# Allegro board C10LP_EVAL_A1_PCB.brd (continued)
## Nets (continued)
C10_M10_IO3: U1.C3(IO, PLL3_CLKOUTN) U3.L5(IO_3_L5/DIFFIO_TX_RX_B1N)
C10_MSEL0: R22.1 R23.1 U1.H13(MSEL0)
C10_MSEL1: R19.1 R20.1 U1.H12(MSEL1)
C10_MSEL2: R17.1 R18.1 U1.G12(MSEL2)
C10_NCE: R8.2 U1.J3(NCE)
C10_NCONFIG: C205.1 R2.2 S1.2 U1.H5(NCONFIG)
C10_NSTATUS: R1.2 U1.F4(NSTATUS) U3.M2(IO_2_M2/DIFFIO_RX_L21P)
C10_RESETN: C204.1 R136.2 S2.2 U1.J15(IO, DIFFIO_R9P, DEV_CLRN)
C10_RG_TXCLK: R305.2 U1.D3(IO, PLL3_CLKOUTP)
C10_RG_TXCTL: R301.2 U1.D6(IO_B8_2)
C10_RG_TXD0: R306.2 U1.E6(IO, DATA6)
C10_RG_TXD1: R303.2 U1.A3(IO, DIFFIO_T2P)
C10_RG_TXD2: R304.2 U1.B3(IO_B8_3)
C10_RG_TXD3: R302.2 U1.A2(IO, DIFFIO_T2N)
C10_USB_CLK: R248.2 U1.B9(CLK9, DIFFCLK_5P)
C10_VCCA: L17.1 R64.1 R67.2
C10_VCCA_FLT: C117.2 L17.2 R4.1 R7.1 R17.2 R19.2 R22.2 U1.F5(VCCA3) U1.F12(VCCA2) U1.L5(VCCA1) U1.L12(VCCA4)
C10_VCCD_PLL: C115.1 R237.2 TP26.1(TP) U1.D4(VCCD_PLL3) U1.D13(VCCD_PLL2) U1.N4(VCCD_PLL1) U1.N13(VCCD_PLL4)
C10_VCCINT: C124.1 C129.1 C130.1 C134.1 C136.1 C138.2 C139.2 C141.1 C142.1 C143.2 C193.1 C194.1 R63.1 R65.2 U1.F7(VCCINT#F7) U1.F11(VCCINT#F11) U1.G6(VCCINT#G6) U1.G7(VCCINT#G7) U1.G8(VCCINT#G8) U1.G9(VCCINT#G9) U1.G10(VCCINT#G10) U1.H6(VCCINT#H6) U1.H11(VCCINT#H11) U1.J6(VCCINT#J6) U1.J12(VCCINT#J12) U1.K7(VCCINT#K7) U1.K9(VCCINT#K9) U1.K10(VCCINT#K10) U1.K11(VCCINT#K11) U1.L6(VCCINT#L6) U1.M9(VCCINT#M9) U1.M11(VCCINT#M11)
C10_VCCIO_1.8V: C122.2 C197.1 R12.1 R236.2 TP25.1(TP) U1.P10(VCCIO4#P10) U1.P13(VCCIO4#P13) U1.T16(VCCIO4#T16)
C10_VCCIO_3.3V: C120.2 C195.1 C196.1 R1.1 R2.1 R16.1 R21.1 R77.1 R78.2 R136.1 R207.1 R246.1 R276.1 R277.1 R278.1 R279.1 R288.1 U1.A1(VCCIO8#A1) U1.A16(VCCIO7#A16) U1.C4(VCCIO8#C4) U1.C7(VCCIO8#C7) U1.C10(VCCIO7#C10) U1.C13(VCCIO7#C13) U1.E3(VCCIO1#E3) U1.E14(VCCIO6#E14) U1.G3(VCCIO1#G3) U1.G14(VCCIO6#G14) U1.K3(VCCIO2#K3) U1.K14(VCCIO5#K14) U1.M3(VCCIO2#M3) U1.M14(VCCIO5#M14) U1.P4(VCCIO3#P4) U1.P7(VCCIO3#P7) U1.T1(VCCIO3#T1)
ENET_CLK_125M: R152.2 U1.T8(CLK14, DIFFCLK_6N)
ENET_INT: R97.1 U1.B5(IO, DIFFIO_T5P) U14.47(MDINT)
ENET_LED0: C55.2 D10.1(ANODE) R109.2 U14.24(LED0)
ENET_LED1: C56.2 D11.1(ANODE) R112.2 U14.23(LED1)
ENET_LED2: C65.2 D12.1(ANODE) R114.2 U14.22(LED2)
ENET_MDC: R297.1 U1.B4(IO, DIFFIO_T3P) U14.41(MDC)
ENET_MDIO: R98.1 U1.A4(IO, DIFFIO_T3N) U14.42(MDIO)
ENET_REGO: L9.2 R95.1 U14.39(REGO)
ENET_RG_RXCLK: R102.1 U1.B8(CLK11, DIFFCLK_4P)
ENET_RG_RXCTL: R103.1 U1.A5(IO, DIFFIO_T5N, DATA7)
ENET_RG_RXD0: R104.1 U1.A7(IO, DIFFIO_T9N)
ENET_RG_RXD1: R105.1 U1.B7(IO, DIFFIO_T9P, DATA4)
ENET_RG_RXD2: R106.1 U1.A6(IO, DIFFIO_T7N)
ENET_RG_RXD3: R107.1 U1.B6(IO, DIFFIO_T7P)
ENET_RG_TXCLK: R305.1 U14.9(TX_CLK)
ENET_RG_TXCTL: R301.1 U14.15(TX_CTL)
ENET_RG_TXD0: R306.1 U14.14(TXD0)
ENET_RG_TXD1: R303.1 U14.12(TXD1)
ENET_RG_TXD2: R304.1 U14.11(TXD2)
ENET_RG_TXD3: R302.1 U14.10(TXD3)
ENET_RSTN: C54.2 R96.1 U1.C6(IO, VREFB8N0) U14.16(RSTN)
ENET_TCK: R99.1 U14.19(TCK)
ENET_TDI: TP6.1(TP) U14.18(TDI)
ENET_TDO: TP5.1(TP) U14.21(TDO)
ENET_TMS: TP7.1(TP) U14.20(TMS)
ENET_VDD_1V: C45.2 C46.1 C48.1 C49.1 C50.2 C51.2 C52.2 L9.1 U14.8(VDDC1) U14.13(VDDC3) U14.17(VDDL) U14.40(VDDC2)
ENET_VDD_3.3V: C57.2 C58.2 C59.1 C60.2 C61.2 C62.2 C63.1 C64.2 R96.2 R97.2 R98.2 R99.2 R100.1 R297.2 R307.2 U14.2(VDDP1) U14.7(VDDP2) U14.25(VDDH1) U14.30(VDDH2) U14.35(VDDH3) U14.38(VDDR) U14.45(VDDP3)
ENET_XTAL1: C44.1 U14.36(XTAL1) Y2.3
ENET_XTAL2: C53.1 U14.37(XTAL2) Y2.1
EXT_JTAG_TCK: J2.1 R57.2 R58.1 U3.J12(IO_5_J12/DIFFIO_RX_R7N)
EXT_JTAG_TDI: J2.9 R61.2 U3.J9(IO_5_J9/DIFFIO_RX_R8P)
EXT_JTAG_TDO: J2.3 U3.K12(IO_5_K12/DIFFIO_RX_R7P)
EXT_JTAG_TMS: J2.5 R60.2 U3.L13(IO_5_L13)
EXT_VREF: C212.1 C213.2 R228.1 R295.2 U3.D3(ADC_VREF__D3)
EXT_VREF_AR: R228.2 R308.2
FX2_D_N: J17.2(D-) U5.2(D-) U6.9(DMINUS)
FX2_D_P: J17.3(D+) U5.1(D+) U6.8(DPLUS)
FX2_FLAGA: U3.M9(IO_3_M9/DIFFIO_RX_B8P) U6.29(CTL0)
FX2_FLAGB: U3.N8(IO_3_N8/DIFFIO_RX_B6P) U6.30(CTL1)
FX2_FLAGC: U3.M8(IO_3_M8/DIFFIO_RX_B8N) U6.31(CTL2)
FX2_PA0: U3.N7(IO_3_N7/DIFFIO_RX_B6N) U6.33(PA0)
FX2_PA1: U3.M7(IO_3_M7/DIFFIO_TX_RX_B5P) U6.34(PA1)
FX2_PA2: U3.N6(IO_3_N6/DIFFIO_TX_RX_B5N) U6.35(PA2)
FX2_PA3: U3.N5(IO_3_N5/DIFFIO_RX_B4P) U6.36(PA3)
FX2_PA4: U3.M5(IO_3_M5/DIFFIO_RX_B2P) U6.37(PA4)
FX2_PA5: U3.N4(IO_3_N4/DIFFIO_RX_B4N) U6.38(PA5)
FX2_PA6: U3.M4(IO_3_M4/DIFFIO_RX_B2N) U6.39(PA6)
FX2_PA7: U3.M3(IO_2_M3/PLL_L_CLKOUTN/DIFFIO_RX) U6.40(PA7)
FX2_PB0: U3.M13(IO_3_M13/DIFFIO_TX_RX_B10N) U6.18(PB0)
FX2_PB1: U3.M12(IO_3_M12/DIFFIO_TX_RX_B10P) U6.19(PB1)
FX2_PB2: U3.N12(IO_3_N12) U6.20(PB2)
FX2_PB3: U3.M11(IO_3_M11/DIFFIO_TX_RX_B12N) U6.21(PB3)
FX2_PB4: U3.L11(IO_3_L11/DIFFIO_TX_RX_B12P) U6.22(PB4)
FX2_PB5: U3.N10(IO_3_N10/DIFFIO_RX_B11N) U6.23(PB5)
FX2_PB6: U3.M10(IO_3_M10/DIFFIO_TX_RX_B16N) U6.24(PB6)
FX2_PB7: U3.N9(IO_3_N9/DIFFIO_RX_B11P) U6.25(PB7)
FX2_PD0: R35.1 U6.45(PD0)
FX2_PD1: R34.1 U6.46(PD1)
FX2_PD2: R36.1 U6.47(PD2)
FX2_PD3: R37.1 U6.48(PD3)
FX2_PD4: U3.J7(IO_3_J7/DIFFIO_TX_RX_B9N) U6.49(PD4)
FX2_PD5: U3.K7(IO_3_K7/DIFFIO_TX_RX_B9P) U6.50(PD5)
FX2_PD6: U3.J5(IO_3_J5/DIFFIO_TX_RX_B3P) U6.51(PD6)
FX2_PD7: U3.L4(IO_3_L4/DIFFIO_TX_RX_B1P) U6.52(PD7)
FX2_RESETN: R27.1 U3.J1(IO_2_J1/DIFFIO_RX_L19N) U4.2(R\E\S\E\T\) U6.42(R\E\S\E\T\)
FX2_SCL: R29.1 U3.J6(IO_3_J6/DIFFIO_TX_RX_B7N) U6.15(SCL)
FX2_SDA: R26.2 R30.1 U6.16(SDA)
FX2_SLRDN: U3.K5(IO_3_K5/DIFFIO_TX_RX_B3N) U6.1(RDY0)
FX2_SLWRN: U3.L3(IO_2_L3/PLL_L_CLKOUTP/DIFFIO_RX) U6.2(RDY1)
FX2_WAKEUP: C14.2 R31.2 R32.2 U6.44(WAKEUP)
GPIO0: J10.1 U1.L13(IO_B5_0)
GPIO1: J10.2 U1.L16(IO, DIFFIO_R11N)
GPIO2: J10.3 U1.L15(IO, DIFFIO_R11P)
GPIO3: J10.4 U1.K16(IO, DIFFIO_R10N)
GPIO4: J10.5 U1.P16(IO, DIFFIO_R15N)
GPIO5: J10.6 U1.R16(IO, DIFFIO_R15P)
GPIO6: J10.7 U1.N16(IO, DIFFIO_R13N)
GPIO7: J10.8 U1.N15(IO, DIFFIO_R13P)
GPIO8: J10.9 U1.N14(IO, RUP3)
GPIO9: J10.10 U1.P15(IO, RDN3)
GPIO10: J10.13 U1.N8(IO_B3_6)
GPIO11: J10.14 U1.P8(IO_B3_7)
GPIO12: J10.15 U1.M8(IO_B3_5)
GPIO13: J10.16 U1.L8(IO_B3_4)
GPIO14: J10.17 U1.R7(IO, DIFFIO_B8P)
GPIO15: J10.18 U1.T7(IO, DIFFIO_B8N)
GPIO16: J10.19 U1.L7(IO_B3_3)
GPIO17: J10.20 U1.M7(IO_B3_2)
GPIO18: J10.21 U1.R6(IO, DIFFIO_B7P)
GPIO19: J10.22 U1.T6(IO, DIFFIO_B7N)
GPIO20: J10.23 U1.T2(IO_B3_0)
GPIO21: J10.24 U1.M6(IO_B3_1)
GPIO22: J10.25 U1.R5(IO, DIFFIO_B6P)
GPIO23: J10.26 U1.T5(IO, DIFFIO_B6N)
GPIO24: J10.27 U1.N5(IO, DIFFIO_B4P)
GPIO25: J10.28 U1.N6(IO, DIFFIO_B4N)
GPIO26: J10.31 U1.R4(IO, PLL1_CLKOUTP)
GPIO27: J10.32 U1.T4(IO, PLL1_CLKOUTN)
GPIO28: J10.33 U1.N3(IO, DIFFIO_B1P)
GPIO29: J10.34 U1.P3(IO, DIFFIO_B1N)
GPIO30: J10.35 U1.R3(IO, DIFFIO_B2P)
GPIO31: J10.36 U1.T3(IO, DIFFIO_B2N)
GPIO32: J10.37 U1.P6(IO, VREFB3N0)
GPIO33: J10.38 U1.P2(IO, DIFFIO_L15P)
GPIO34: J10.39 U1.P1(IO, DIFFIO_L15N)
GPIO35: J10.40 U1.R1(IO_B2_0)
HBUS_CKN: R243.1 U1.R14(IO, PLL4_CLKOUTN) U13.B1(CK#)
HBUS_CKP: R243.2 U1.P14(IO, PLL4_CLKOUTP) U13.B2(CK)
HBUS_CLK_50M: R157.2 U1.M15(CLK6, DIFFCLK_3P)
HBUS_CS1N: R258.2 U1.N12(IO_B4_2)
HBUS_CS2N: U1.P9(IO_B4_1) U13.A3(CS#)
HBUS_DQ0: R249.1 U1.T12(IO, DIFFIO_B18N)
HBUS_DQ1: R250.1 U1.T13(IO, DIFFIO_B20N)
HBUS_DQ2: R251.1 U1.T11(IO, DIFFIO_B17N)
HBUS_DQ3: R252.1 U1.R10(IO, DIFFIO_B16P)
HBUS_DQ4: R253.1 U1.T10(IO, DIFFIO_B16N)
HBUS_DQ5: R254.1 U1.R11(IO, DIFFIO_B17P)
HBUS_DQ6: R255.1 U1.R12(IO, DIFFIO_B18P)
HBUS_DQ7: R256.1 U1.R13(IO, DIFFIO_B20P)
HBUS_INTN: R260.2 R262.1 U1.P11(IO, VREFB4N0)
HBUS_RSTN: R245.1 U1.N9(IO_B4_0) U13.A4(RESET#)
HBUS_RSTON: R259.2 R261.1 U1.T15(IO, DIFFIO_B23N)
HBUS_RWDS: R257.1 U1.T14(IO, DIFFIO_B23P)
IOREF: J4.2 R280.2
M10_CLK50M: R160.2 U3.H5(IO_2_H5/CLK1N/DIFFIO_RX_L20N)
M10_CLK50M_R: R160.1 U20.4(CLKP/1)
M10_CONF_DONE: R43.2 U3.C5(IO_8_C5/CONF_DONE/DIFFIO_RX_T24)
M10_CONFIG_SEL: R40.2 R50.1 U3.D7(IO_8_D7/CONFIG_SEL)
M10_DEV_CLRN: R38.2 U3.B9(IO_8_B9/DEV_CLRN/DIFFIO_RX_T16N)
M10_DEV_OE: R39.2 U3.D8(IO_8_D8/DEV_OE/DIFFIO_RX_T18P)
M10_JTAGEN: R33.2 U3.E5(IO_1B_E5/JTAGEN)
M10_NCONFIG: R41.2 U3.E7(INPUT_ONLY_8_E7/NCONFIG)
M10_NSTATUS: R42.2 U3.C4(IO_8_C4/NSTATUS/DIFFIO_RX_T24P)
M10_TCK: J1.1 R35.2 R44.2 R45.1 U3.G2(IO_1B_G2/TCK/DIFFIO_RX_L11P)
M10_TDI: J1.9 R36.2 R47.2 U3.F5(IO_1B_F5/TDI/DIFFIO_RX_L12N)
M10_TDO: J1.3 R37.2 U3.F6(IO_1B_F6/TDO/DIFFIO_RX_L12P)
M10_TMS: J1.5 R34.2 R46.2 U3.G1(IO_1B_G1/TMS/DIFFIO_RX_L11N)
M10_USB_CLK: R247.1 U3.G5(IO_2_G5/CLK0N/DIFFIO_RX_L18N)
M10_VCCA_3.3V: C19.2 C23.2 C26.2 C168.1 C173.1 C177.1 C178.2 C179.2 C180.2 C181.2 C188.1 L3.2 U3.D4(VCCA3__D4) U3.D10(VCCA2__D10) U3.K4(VCCA1__K4) U3.K9(VCCA4__K9) U7.2(V+) U8.2(V+) U11.2(V+) U32.8(VDD) U33.8(VDD) U34.8(VDD)
M10_VCCIO1A: C156.1 C176.1 L2.2 U3.F2(VCCIO1A__F2)
MAX_SDA: R26.1 U3.K6(IO_3_K6/DIFFIO_TX_RX_B7P)
MX1+: J16.1(1+) U28.13(MX4-)
MX1-: J16.2(1-) U28.14(MX4+)
MX2+: J16.3(2+) U28.16(MX3-)
MX2-: J16.6(2-) U28.17(MX3+)
MX3+: J16.4(3+) U28.19(MX2-)
MX3-: J16.5(3-) U28.20(MX2+)
MX4+: J16.7(4+) U28.22(MX1-)
MX4-: J16.8(4-) U28.23(MX1+)
PMOD_D0: R116.1 U1.D16(IO_B6_2)
PMOD_D1: R118.1 U1.F13(IO_B6_0)
PMOD_D2: R120.1 U1.D15(IO_B6_3)
PMOD_D3: R122.1 U1.F16(IO, DIFFIO_R4N, NCEO)
PMOD_D4: R117.2 U1.C16(IO, DIFFIO_R1N)
PMOD_D5: R119.2 U1.F15(IO, DIFFIO_R4P, CLKUSR)
PMOD_D6: R121.2 U1.C15(IO, DIFFIO_R1P)
PMOD_D7: R123.2 U1.B16(IO_B6_1)
PMOD_IO0: J8.1 R116.2 U15.1(IO1)
PMOD_IO1: J8.2 R118.2 U15.3(IO2)
PMOD_IO2: J8.3 R120.2 R270.1 U15.4(IO3)
PMOD_IO3: J8.4 R122.2 R269.1 U15.6(IO4)
PMOD_IO4: J8.7 R117.1 U16.1(IO1)
PMOD_IO5: J8.8 R119.1 U16.3(IO2)
PMOD_IO6: J8.9 R121.1 R265.1 U16.4(IO3)
PMOD_IO7: J8.10 R123.1 R266.1 U16.6(IO4)
PWR_GD_LED: Q5.1(GATE) U3.H9(IO_5_H9/DIFFIO_RX_R10P)
RDN2: R13.2 U1.N11(IO, RDN2)
REG_PG_LED_R: D4.1(ANODE) R235.2
RG_RXCLK: R102.2 U14.6(RX_CLK)
RG_RXCTL: R103.2 U14.48(RX_CTL)
RG_RXD0: R104.2 U14.5(RXD0)
RG_RXD1: R105.2 U14.4(RXD1)
RG_RXD2: R106.2 U14.3(RXD2)
RG_RXD3: R107.2 U14.1(RXD3)
RUP2: R12.2 U1.M10(IO, RUP2)
SYS_CONF_DONE: D5.2(CATHODE) U3.K1(IO_2_K1/DIFFIO_RX_L28N)
SYS_CONF_DONE_R: D5.1(ANODE) R135.2
SYS_I2C_SCL: R55.2 R263.1 U3.G13(IO_5_G13/DIFFIO_RX_R11P)
SYS_I2C_SDA: R56.2 R264.1 U3.H8(IO_5_H8/DIFFIO_RX_R10N)
TPIAN: U14.27(TPIAN) U28.11(TD4+)
TPIAP: U14.26(TPIAP) U28.12(TD4-)
TPIBN: U14.29(TPIBN) U28.8(TD3+)
TPIBP: U14.28(TPIBP) U28.9(TD3-)
TPICN: R108.2 U14.32(TPICN) U28.5(TD2+)
TPICP: R110.2 U14.31(TPICP) U28.6(TD2-)
TPIDN: U14.34(TPIDN) U28.2(TD1+)
TPIDP: U14.33(TPIDP) U28.3(TD1-)
USB_5V: D20.2(ANODE) J17.1(VBUS) Q30.D R31.1 R165.1
USB_ADDR0: U1.A10(IO, DIFFIO_T16N) U3.A7(IO_8_A7/DIFFIO_RX_T19P)
USB_ADDR1: U1.A11(IO, DIFFIO_T20N) U3.A10(IO_8_A10/DIFFIO_RX_T17P)
USB_CLK: R247.2 R248.1 U6.13(IFCLK)
USB_DATA0: U1.A15(IO_B7_0) U3.A3(IO_8_A3/DIFFIO_RX_T21N)
USB_DATA1: U1.B14(IO, PLL2_CLKOUTP) U3.B3(IO_8_B3/DIFFIO_RX_T23P)
USB_DATA2: U1.A14(IO, PLL2_CLKOUTN) U3.A4(IO_8_A4/DIFFIO_RX_T21P)
USB_DATA3: U1.B13(IO, DIFFIO_T22P) U3.B4(IO_8_B4/DIFFIO_RX_T23N)
USB_DATA4: U1.A13(IO, DIFFIO_T22N) U3.A5(IO_8_A5)
USB_DATA5: U1.B12(IO, DIFFIO_T21P) U3.B5(IO_8_B5/DIFFIO_RX_T20N)
USB_DATA6: U1.A12(IO, DIFFIO_T21N) U3.A6(IO_8_A6/DIFFIO_RX_T19N)
USB_DATA7: U1.B10(IO, DIFFIO_T16P) U3.B6(IO_8_B6/DIFFIO_RX_T20P)
USB_DISABLEN: J2.2 R59.1 U3.J13(IO_5_J13/DIFFIO_RX_R9P)
USB_EMPTY: R52.1 U1.D14(IO, DIFFIO_T24P) U3.E6(IO_8_E6/DIFFIO_RX_T22P)
USB_FULL: R51.1 U1.D12(IO, DIFFIO_T23P) U3.C9(IO_8_C9/DIFFIO_RX_T14N)
USB_OEN: U1.F9(IO_B7_1) U3.A9(IO_8_A9/DIFFIO_RX_T15N)
USB_RDN: U1.D11(IO, DIFFIO_T23N) U3.B10(IO_8_B10/DIFFIO_RX_T16P)
USB_RESETN: U1.C9(IO, DIFFIO_T15N) U3.A8(IO_8_A8/DIFFIO_RX_T15P)
USB_SCL: R54.1 U1.C14(IO, DIFFIO_T24N) U3.E8(IO_8_E8/DIFFIO_RX_T18N)
USB_SDA: R53.1 U1.E9(IO_B7_2) U3.C10(IO_8_C10/DIFFIO_RX_T14P)
USB_WRN: U1.B11(IO, DIFFIO_T20P) U3.A11(IO_8_A11/DIFFIO_RX_T17N)
USER_DIP0: R147.1 SW1.6(B3) U1.M16(CLK7, DIFFCLK_3N)
USER_DIP1: R146.1 SW1.7(B2) U1.A8(CLK10, DIFFCLK_4N)
USER_DIP2: R145.1 SW1.8(B1) U1.A9(CLK8, DIFFCLK_5N)
USER_LED0: D6.2(CATHODE) U1.L14(IO, VREFB5N0)
USER_LED0_R: D6.1(ANODE) R138.2
USER_LED1: D7.2(CATHODE) U1.K15(IO, DIFFIO_R10P)
USER_LED1_R: D7.1(ANODE) R140.2
USER_LED2: D8.2(CATHODE) U1.J14(IO_B5_1)
USER_LED2_R: D8.1(ANODE) R142.2
USER_LED3: D9.2(CATHODE) U1.J13(IO_B5_2)
USER_LED3_R: D9.1(ANODE) R143.2
USER_PB0: C206.1 R137.1 S3.2 U1.E15(CLK4, DIFFCLK_2P)
USER_PB1: C207.1 R139.1 S4.2 U1.F14(IO, VREFB6N0)
USER_PB2: C208.1 R141.1 S5.2 U1.C11(IO, VREFB7N0)
USER_PB3: C209.1 R144.1 S6.2 U1.D9(IO, DIFFIO_T15P)
VTAP_BYPASSN: R148.1 SW1.5(B4) U3.K10(IO_5_K10/DIFFIO_RX_R1P)
XA: C66.2 U31.2(XA) Y3.3
XB: C73.2 U31.3(XB) Y3.1
N16637352: R92.2 U13.A1(VSS1/DNP)
N16666559: C47.1 R95.2
N16670783: R100.2 U14.43(SCL)
N16798884: C15.2 R44.1
N16807169: R101.2 U14.44(SDA)
N16863501: R65.1 U7.1(-IN)
N16863513: R66.1 U7.8(+IN)
N16863764: R67.1 U8.1(-IN)
N16863768: R68.1 U8.8(+IN)
N16887336: R11.1 U2.9(VCC/DATA2)
N16887348: R9.2 U2.1(VCC/DATA3)
N16887422: R10.2 U2.8(DATA1)
N16986323: R208.1 U28.15(MCT4)
N16986325: R209.1 U28.18(MCT3)
N16986327: R210.1 U28.21(MCT2)
N16986329: R211.1 U28.24(MCT1)
N16986355: C159.1 R208.2 R209.2 R210.2 R211.2
N16993975: J17.4(ID) R213.1
N17040639: R79.1 U11.8(+IN)
N17040659: R78.1 U11.1(-IN)
N17050331: C30.1 L5.2 U12.1(VIN)
N17106026: D10.2(CATHODE) R240.2
N17106333: D11.2(CATHODE) R241.2
N17106465: D12.2(CATHODE) R242.2
N17132385: R249.2 U13.D3(DQ0)
N17132392: R250.2 U13.D2(DQ1)
N17132399: R251.2 U13.C4(DQ2)
N17132406: R252.2 U13.D4(DQ3)
N17132413: R253.2 U13.D5(DQ4)
N17132420: R254.2 U13.E3(DQ5)
N17132427: R255.2 U13.E2(DQ6)
N17132434: R256.2 U13.E1(DQ7)
N17132441: R257.2 U13.C3(RWDS)
N17204392: R258.1 U13.C2(RFU4)
N17217821: R259.1 U13.A2(RFU1)
N17217865: R260.1 U13.A5(RFU2)
N17225816: R192.1 R201.1
N17241873: J4.8 R275.1
N17244926: C160.1 U28.10(TCT4)
N17244940: C161.1 U28.7(TCT3)
N17244954: C162.1 U28.4(TCT2)
N17244968: C163.1 U28.1(TCT1)
N17285342: C67.2 L10.2 U31.1(VDD)
N17285440: R264.2 U31.5(SDA)
N17285442: R263.2 U31.4(SCL)
N17285490: R152.1 U31.10(CLK0)
N17285492: R155.1 U31.9(CLK1)
N17285494: R157.1 U31.6(CLK2)
N17285521: C72.2 L16.1 U31.7(VDDO)
N17451710: C17.2 R57.1
N17472668: D28.3(CATHODE) R289.2 R290.2
N17473523: C200.1 C201.2 Q29.3(C) R291.1 R292.2 R294.2
N17473566: Q29.1(B) R290.1
N17490351: Q15.G R294.1
N17512425: C31.1 R295.1 U12.2(VOUT)
N17533679: L15.2 R237.1 TP27.1(TP)
N17554452: C210.1 R298.1 R299.2 R300.2
N17555511: Q30.G R299.1
N17689344: D4.2(CATHODE) Q5.3(DRAIN) R309.2

Pads without a net: D28 2; J1 6 7 8; J2 6 7 8; J4 1; NOREF#2 1; NOREF#3 1; NOREF#4 1; NOREF#6 1; NOREF#8 1; NOREF#12 1; NOREF#15 1; NOREF#16 1; NOREF#17 1; NOREF#18 1; NOREF#21 1; NOREF#25 1; NOREF#26 1; NOREF#27 1; NOREF#28 1; NOREF#29 1; NOREF#30 1; NOREF#31 1; NOREF#32 1; U1 E10 E11; U2 3 4 5 6 11 12 13 14; U3 A2 B2 B7 B11 B12 B13 C11 C12 C13 D6 D11 D13 E9 E12 F4 F8 F12 G4 G12 H1 H2 H3 J2 J10 K13 L1 N11; U4 3; U6 54; U7 3 6 7; U8 3 6 7; U11 3 6 7; U13 B5 C5; U14 46; U20 1; U23 1 13 21 22 23 24; U25 1 13 21 22 23 24; U26 1 4 15 16; U27 1 4 15 16

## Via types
v1: diameter 0.559, hole 0.254, TOP to BOTTOM, 700 vias
v2: diameter 0.406, hole 0.203, TOP to BOTTOM, 262 vias
v3: diameter 0.61, hole 0.305, TOP to BOTTOM, 94 vias
v4: diameter 0.635, hole 0.33, TOP to BOTTOM, 9 vias

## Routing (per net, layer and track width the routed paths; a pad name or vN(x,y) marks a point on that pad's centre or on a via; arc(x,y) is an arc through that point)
1.8V_VSENSE: length 6.4
  TOP w0.203: U26.5 33.21,11.06 33.48,11.33 33.48,15.81 R197.2 C104.2
2.5V_VSENSE: length 7.1
  BOTTOM w0.203: R198.2 C103.2 36.46,61.52 31.47,61.52 31.23,61.27 U27.5
3.3V_SI510: length 10.6
  TOP w0.508: L12.2 40.37,47.23 C74.2 40.37,49.77 v1(40.18,49.96)
  BOTTOM w0.508: U20.2 38.2,45.49 39.52,46.81 39.85,46.81 40.74,47.7 U20.6 40.18,48.79 v1(40.18,49.96)
5V_DCIN:
  vias: v1(65.43,83.11) v1(65.43,82.42) v1(65.46,81.74) v1(66.14,83.11) v1(66.14,82.42) v1(66.14,81.74) v1(66.83,82.45) v1(66.83,81.74) v1(67.51,82.42) v1(67.51,81.74)
GND: length 278.4
  TOP w0.135: U1.M1 v2(34.24,27.28) ; U1.M2 v2(35.04,27.28)
  TOP w0.137: U1.R8 40.64,24.88 v1(40.64,23.57)
  TOP w0.203: U5.3 v1(70.46,70.44) ; C53.2 21.98,56.07 v1(21.62,56.44)
  TOP w0.254: v1(68.48,65.66) 69.47,65.66 v1(69.95,66.14) 71.58,66.14 71.86,66.42 v1(71.86,68.52) ; v1(46.74,15.09) 46.57,15.09 v1(46.09,14.61) ; U6.6 65.36,69.19 65.28,69.27 v1(65.18,69.27) ; 60.75,72.37 60.75,73.22 60.71,73.26 U6.26 ; 60.75,72.37 60.5,72.37 59.77,73.1 59.77,73.38 59.71,73.43 U6.28 ; 60.75,72.37 v1(60.75,72.09) ; U6.14 66.31,73.19 65.31,72.19 ; U6.56 66.21,66.5 65.53,67.18 65.53,67.34 65.12,67.75 ; U6.10 65.47,71.19 v1(65.15,70.88) ; U6.53 64.71,66.74 64.72,66.75 64.72,67.05 64.97,67.31 65.12,67.31 v1(65.12,67.83) ; 65.31,72.19 U6.12 ; 65.31,72.19 65.21,72.09 v1(65.17,72.09) ; v1(58.27,67.18) 58.28,67.19 U6.41 ; v1(21.62,56.44) 21.62,58.6 22.05,59.03 v1(22.62,59.03) 24.49,59.03 24.94,58.57 v1(24.94,56.92) 24.94,55.82 C44.2 ; Y1.4 70.83,68.67 70.1,69.39 v1(69.14,69.39)
  TOP w0.305: v1(79.98,39.12) v1(79.98,42.42) v1(79.98,44.48) ; v1(79.98,39.12) v1(79.98,37.21) v1(79.98,34.32) v1(79.98,32) v1(79.98,29.24) ; v1(79.98,39.12) 79.76,38.89 77.72,38.89 76.85,38.01 S3.1 ; C102.2 49.75,16.48 v1(50.22,16.48) 50.67,16.48 v1(50.88,16.69) 50.89,16.7 ; v2(46.24,36.08) U1.B15 ; v1(68.48,64.74) 69.38,64.74 R213.2 ; 75.69,55.24 75.74,55.3 SW1.4 77.83,55.3 77.9,55.37 ; U3.F13 42.2,64.27 v2(41.68,63.75) ; v2(46.1,64.64) 46.1,64.63 U3.F9 ; U3.F10 45.34,63.88 v2(45.34,63.88) ; v2(36.65,27.28) 37.04,27.67 U1.M4 ; U1.C5 37.84,34.88 v2(37.44,35.28) ; U1.M13 v2(43.84,27.28) ; v1(66.9,29.96) 67.51,29.96 C208.2 ; v2(42.24,28.08) U1.L10 ; v1(79.98,44.48) v1(79.98,52.81) v1(79.98,56.08) 79.26,56.08 R309.1 ; v1(79.98,44.48) 79.6,44.09 76.76,44.09 76.46,43.79 S2.1 ; 75.69,52.78 75.72,52.76 SW1.2 ; v1(42.4,70.53) 42.55,70.38 U3.N13 ; R201.2 50.5,17.28 U25.15 ; U3.N3 50.55,69.88 v2(50.55,70.48) ; C204.2 v1(66.88,43.42) ; C74.1 41.12,48.98 v1(41.12,49.96) ; v2(38.24,32.88) U1.F6 ; U13.E5 40.88,17.16 v1(40.84,17.2) ; C143.1 49.94,25.56 49.94,24.99 49.68,24.74 v1(49.68,24.66) ; C205.2 v1(66.88,47.74) ; v2(37.44,32.08) U1.G5 ; v2(36.64,32.08) U1.G4 ; U3.B8 v2(46.95,60.67) ; U3.J4 v2(50.15,67.07) ; v2(41.71,62.94) 42.24,63.47 U3.E13 ; U3.F3 v2(50.95,63.87) ; v2(42.24,31.28) U1.H10 ; v2(43.84,28.88) U1.K12 ; U1.N10 42.21,26.51 v2(42.21,26.49) ; U13.C1 45.54,15.16 v1(46.09,14.61) ; v2(52.55,70.28) 52.15,69.88 U3.N1 ; v2(41.44,28.08) U1.L9 ; U2.10 v1(27.1,36.22) ; U3.G7 v2(47.75,65.48) ; v2(44.64,28.88) U1.K13 ; v2(41.44,31.28) U1.H9 ; v2(35.04,24.88) U1.R2 ; v2(44.64,32.08) U1.G13 ; C206.2 67.14,38.85 v1(66.85,39.14) ; v2(42.24,32.88) U1.F10 ; v2(42.95,65.47) U3.H12 ; U1.T9 41.42,24.11 v2(41.42,24.09) ; v2(37.44,27.28) U1.M5 ; v2(43.04,27.28) U1.M12 ; SW1.1 75.59,51.49 75.56,51.46 ; v2(36.64,28.88) U1.K4 ; v2(39.84,28.88) U1.K8 ; v2(36.64,33.68) U1.E4 ; U13.B3 44.01,13.68 v1(44.02,13.68) ; v2(41.44,29.68) U1.J9 ; U1.E13 44.24,33.29 v2(44.63,33.68) ; v2(39.04,31.28) U1.H7 ; v2(47.04,31.28) U1.H16 ; v1(34.53,57.19) C65.1 R114.1 ; v1(75.51,54.28) 75.77,54.03 SW1.3 ; U3.N2 v2(51.75,70.28) ; v2(39.84,31.28) U1.H8 ; v2(43.84,25.68) U1.P12 ; U3.H4 v2(50.15,66.28) ; C209.2 v1(66.9,25.64) ; S1.1 v1(76.46,48.26) ; U3.G9 v2(45.35,65.48) ; U3.A13 v2(42.15,59.87) ; v2(43.04,28.08) U1.L11 ; v2(52.15,59.72) U3.A1 ; v2(42.24,29.68) U1.J10 ; U3.M6 v2(48.55,69.48) ; v2(39.84,29.68) U1.J8 ; v2(42.24,34.48) U1.D10 ; v2(38.24,28.88) U1.K6 ; U1.E12 43.44,33.29 v2(43.83,33.68) ; v1(66.88,34.33) 67.51,34.33 C207.2 ; R108.1 26.72,57.33 v1(26.54,57.51) ; v2(43.04,29.68) U1.J11 ; v2(35.04,33.68) U1.E2 ; v2(46.24,24.88) U1.R15 ; v2(37.44,34.48) U1.D5 ; v2(46.24,31.28) U1.H15 ; U1.R9 41.42,24.91 v2(41.42,24.89) ; U3.D5 v2(49.35,62.27) ; v2(35.04,32.88) U1.F2 ; U3.H6 v2(48.55,66.28) ; U3.G10 v2(44.55,65.48) ; U3.L9 v2(45.35,68.67) ; v2(43.84,35.28) U1.C12 ; v2(39.04,34.48) U1.D7 ; v2(39.04,26.48) U1.N7 ; v2(37.44,33.68) U1.E5 ; v2(35.04,36.08) U1.B2 ; U3.E11 v2(43.75,63.87) ; v2(37.44,25.68) U1.P5 ; v2(39.04,29.68) U1.J7 ; R110.1 v1(27.99,57.43) ; U3.C3 v2(50.15,61.47) ; v2(43.04,32.08) U1.G11 ; v2(34.24,32.88) U1.F1
  TOP w0.33: v1(40.34,17.7) v1(40.84,17.2)
  TOP w0.381: R6.2 29.53,32.54 v1(29.53,33.02) ; v1(23.8,53.98) 23.15,54.62 C64.1 22.59,55.07 v1(22.2,55.07) ; v1(51.03,12.9) 51.23,13.11 51.67,13.11 C101.1 ; R92.1 v1(49.09,11.49) ; C47.2 v1(20.07,57.94) ; C18.1 46.23,74.65 v1(46.18,74.7) ; v1(53.77,84.23) 54.32,84.23 C17.1 ; C55.1 R109.1 31.18,55.77 v1(31.17,55.75) ; R58.2 v1(55.36,80.43)
  TOP w0.406: C4.2 69.1,69.35 v1(69.14,69.39) ; R201.2 50.48,17.08 v1(50.88,16.69) ; C54.1 34.92,49.11 v1(34.92,49.73) ; v1(24.94,56.92) 24.93,56.93 Y2.2 ; Y1.2 69.95,66.8 v1(69.95,66.14) ; S4.1 74.18,33.59 v1(73.86,33.92) ; v1(68.48,65.66) C5.2 ; Y1.4 v1(71.86,68.52) ; Y2.4 v1(22.62,59.03) ; S5.1 74.62,29.18 v1(74.61,29.17) ; C114.1 34.95,7.11 v1(35.69,6.38) ; S6.1 v1(76.46,26.13)
  TOP w0.508: J2.10 v1(40.28,79.68)
  BOTTOM w0.203: U27.10 29.12,61.27 v2(29.26,61.42) 29,61.67 U27.11
  BOTTOM w0.254: v1(75.51,54.28) 75.53,54.29 R298.2 ; C72.1 76.06,22.59 76.32,22.85 U31.8
  BOTTOM w0.305: R8.1 30.53,27.7 30.84,28 v1(30.84,29.36) ; C153.1 47.52,65.25 v2(47.75,65.48) ; v2(45.35,68.67) 45.01,69.01 45.01,69.24 44.66,69.59 C180.1 ; C142.2 50.65,25.65 51.23,25.07 v1(51.23,22.89) ; v2(41.71,62.94) 41.79,62.94 C179.1 ; v1(26.59,59.31) 26.77,59.49 C113.1 ; v1(49.68,24.66) 49.68,25.02 49.48,25.22 C130.2 ; C189.2 42.36,63.51 42.11,63.75 v2(41.68,63.75) ; v2(45.35,65.48) 44.96,65.09 44.96,64.78 C182.2 ; C157.1 49.55,64.91 50.15,65.51 v2(50.15,66.28) ; C155.1 42.86,70.01 42.86,70.07 v1(42.4,70.53) ; v1(74.61,29.17) C66.1 74.14,29.97 73.84,30.28 73.84,33.9 v1(73.86,33.92) Y3.4 ; v2(51.75,70.28) 51.59,70.12 C178.1 ; R40.1 46.95,59.67 v2(46.95,60.67) ; Y3.4 75.54,33.35 75.54,32.97 76.1,32.41 76.1,32.19 Y3.2 ; Y3.4 74.97,34.82 75.17,35.03 77.44,35.03 78.13,34.34 v1(78.13,31.75) 78.13,30.84 77.53,30.24 C73.1 ; v1(29.13,18.87) 29.13,18.99 R181.1 ; v1(39.37,75.21) 39.83,74.75 C16.1 ; v1(50.57,27.64) 50.57,28.35 51.24,29.02 R23.2 ; R18.2 v1(48.29,35.05) ; C1.2 v1(23.93,29.16) ; R13.1 45.39,21.6 v1(45.39,22.28) ; R20.2 51.24,33.85 v1(50.9,34.19) ; v1(51.31,20.29) 51.28,20.29 50.61,20.97 C193.2 ; C151.2 46.03,64.57 v2(46.1,64.64) ; C89.2 27.13,18.54 26.84,18.83 U23.15 ; v2(50.95,63.87) 51.71,64.64 C156.2 ; v1(73.79,27.64) C67.1 ; R112.1 C56.1 v1(14.92,56.68) ; C11.1 59.63,64.25 v1(59.87,64.49) ; v1(39.95,66.4) 39.95,66.45 40.34,66.83 C146.2 ; R27.2 59.23,66.31 U4.1 58.7,67.18 v1(58.27,67.18) ; C194.2 v1(48.56,20.14) ; C51.1 v1(27.24,43.57)
  BOTTOM w0.381: U15.2 v1(79.4,17.98) ; C52.1 19.25,51.18 v1(18.57,51.87) ; R240.1 v1(13.8,56.86) ; R241.1 14.5,59.23 v1(15.39,60.12) ; C89.2 27.83,18.69 v1(28.45,18.69) ; R242.1 v1(13.8,61.73) ; C88.1 v1(24.89,13.97) ; R45.2 v1(36.21,82.37) ; C15.1 v1(37.87,84.12)
  BOTTOM w0.406: v2(41.44,29.68) 41.22,29.46 C134.2 ; C176.2 53.64,68.68 v1(53.77,68.81) ; C120.1 34.53,35.11 35.04,35.62 v2(35.04,36.08) ; v2(46.24,31.28) 45.44,30.48 C136.2 ; C196.2 38.03,25.09 v2(37.44,25.68) ; C129.2 41.26,24.92 41.39,24.92 v2(41.42,24.89) ; C138.1 41.84,30.08 v2(42.24,29.68) ; v1(46.15,72.9) 46.15,71.93 C190.2 ; v2(41.42,24.09) 41.6,23.91 C197.2 ; v2(41.43,35.31) 40.69,34.57 C124.2 ; v2(39.04,29.68) 39.44,30.08 C139.1 ; C117.1 46.66,35.66 v2(46.24,36.08) ; C122.1 43.7,25.54 v2(43.84,25.68) ; v2(53.06,62.23) 52.11,62.23 C181.1 ; v2(41.44,31.28) 40.83,30.67 C141.2
  BOTTOM w0.508: C160.2 v1(34.62,80.04) ; C161.2 v1(34.52,76.23) ; C163.2 v1(34.52,68.61) ; C162.2 v1(34.72,72.42) ; U20.3 v1(35.66,45.69) ; v1(74.42,9.73) U16.2 ; J2.10 v1(40.28,79.68) ; R101.1 22.23,47.55 21.92,47.24 v1(21.49,47.24) ; v1(52.2,78.99) 50.95,78.99 50.44,78.49 J1.10
  vias: v1(1.3,57.12) v1(1.3,54.61) v1(1.3,52.07) v1(1.3,49.56) v1(1.3,46.99) v1(1.3,44.35) v1(1.3,42.04) v1(1.3,39.4) v1(1.3,36.83) v1(1.3,34.29) v1(1.3,31.75) v1(1.3,29.21) v1(1.3,26.67) v1(1.3,24.13) v1(1.3,21.46) v1(1.3,19.18) v1(1.3,16.51) v1(1.3,13.97) v1(1.3,11.43) v1(1.3,8.89) v1(1.3,6.38) v1(2.67,6.38) v1(5.21,6.38) v1(7.75,6.38) v1(10.13,65.53) v1(10.11,64.31) v1(10.06,63.17) v1(10.16,66.47) v1(10.29,6.38) v1(12.83,6.38) v1(15.37,6.38) v1(17.91,6.38) v1(18.52,52.83) v1(19.08,46.28) v1(20.17,46.3) v1(20.35,38.89) v1(20.32,34.9) v1(21.21,19.05) v1(21.9,19.05) v1(22.61,19.05) v1(23.47,20.12) v1(23.5,18.97) v1(24.33,19.5) v1(24.38,45.92) v1(24.36,6.38) v1(25.12,18.95) v1(25.2,20.09) v1(25.53,6.38) v1(25.7,52.78) v1(25.7,51.66) v1(25.7,50.57) v1(25.7,49.48) v1(25.7,48.36) v1(26.92,52.76) v1(26.97,51.66) v1(27,50.6) v1(27.03,49.45) v1(27,48.34) v1(28.07,6.38) v1(28.4,52.76) v1(28.37,51.71) v1(28.4,50.57) v1(28.5,49.43) v1(28.52,48.36) v1(29.97,52.73) v1(30,51.61) v1(29.97,50.57) v1(30,49.48) v1(30,48.36) v1(30.61,6.38) v1(31.34,64.82) v1(31.34,64.11) v1(31.37,60.63) v1(32,10.52) v1(32.11,64.82) v1(32.08,64.11) v1(33.15,6.38) v1(34.16,85.06) v1(36.7,85.06) v1(38.23,6.38) v1(38.4,18.62) v1(38.43,17.91) v1(40.77,6.38) v1(43.31,6.38) v1(45.85,6.38) v1(45.95,46.48) v1(45.95,45.8) v1(45.97,47.19) v1(46.48,13.11) v1(48.39,6.38) v1(49.15,84.96) v1(49.38,14.05) v1(50.93,6.38) v1(53.47,6.38) v1(53.72,85.06) v1(56.01,6.38) v1(56.26,85.06) v1(57.71,15.88) v1(58.01,15.06) v1(58.22,85.06) v1(58.55,6.38) v1(58.65,15.54) v1(58.81,16.59) v1(59.61,16.61) v1(59.66,15.88) v1(60.4,61.57) v1(60.43,18.14) v1(60.38,16.64) v1(60.45,15.93) v1(60.73,70.8) v1(60.75,69.27) v1(60.75,67.8) v1(60.78,60.91) v1(61.09,61.57) v1(61.14,18.11) v1(61.11,16.61) v1(61.84,70.77) v1(61.82,69.3) v1(61.87,72.09) v1(61.87,67.8) v1(62.96,72.09) v1(62.99,70.8) v1(62.97,69.27) v1(62.96,67.83) v1(64,67.8) v1(64.05,72.09) v1(64.05,70.82) v1(64.14,69.27) v1(64.16,85.06) v1(64.34,6.53) v1(65.35,60.12) v1(66.07,60.12) v1(66.22,85.06) v1(66.17,6.38) v1(68.2,85.06) v1(68.63,41.25) v1(68.63,40.56) v1(68.63,39.88) v1(68.71,43.84) v1(68.66,39.19) v1(68.68,36.75) v1(68.68,36.07) v1(69.32,41.25) v1(69.32,40.56) v1(69.32,39.88) v1(69.34,39.19) v1(69.39,43.84) v1(69.37,36.75) v1(69.37,36.07) v1(70.13,85.04) v1(70.33,54.28) v1(70.33,53.54) v1(71.04,54.28) v1(71.04,53.54) v1(71.88,85.06) v1(73.48,6.38) v1(73.61,85.04) v1(74.73,22.02) v1(74.73,21.34) v1(75.23,6.38) v1(75.41,22.02) v1(75.44,21.34) v1(75.49,53.29) v1(77.01,6.38) v1(78.59,6.38) v1(79.98,59.79) v1(79.98,26.7) v1(79.98,24.16) v1(79.98,21.62) v1(79.98,19.08) v1(79.98,16.54) v1(79.98,14) v1(79.98,11.46) v1(79.98,8.92) v1(79.98,6.38) v3(18.54,19.15) v3(18.85,16.71) v3(19.02,14.07) v3(19.35,19.18) v3(19.71,16.71) v3(19.96,14.15) v3(23.24,22.1) v3(24.16,26.72) v3(24.51,24.26) v3(24.66,26.06) v3(24.74,23.52) v3(24.97,26.75) v3(25.25,24.23) v3(25.43,26.09) v3(25.53,23.52) v3(36.31,12.41) v3(36.31,11.64) v3(37.07,12.41) v3(37.07,11.64) v3(37.26,14.43) v3(37.26,13.69) v3(37.83,12.41) v3(37.83,11.64) v3(38,14.43) v3(38,13.69) v3(52.58,21.72) v3(52.58,20.85) v3(53.34,25.17) v3(53.34,24.44) v3(53.34,23.7) v3(53.34,21.72) v3(53.34,20.85) v3(72.26,75.31) v3(72.26,74.3) v3(73.15,75.31) v3(73.15,74.3) v3(74.04,75.31) v3(74.04,74.3) v4(52.81,17.92) v4(53.34,18.49) v4(53.34,17.35) v4(53.97,17.92) v4(54.49,18.49) v4(54.49,17.35) v4(55.25,17.6) v4(56.01,17.35) v4(56.77,17.6)
VCC_1.2V: length 37.7
  TOP w0.254: R66.2 v1(58.92,36.13) ; v3(58.93,24.21) 58.93,24.38 56.87,26.44 53.52,26.44 52.32,25.25 52.32,22.92 50.63,21.23 49.85,21.23 49.59,20.98 R191.2
  TOP w0.305: C97.1 R191.2
  BOTTOM w0.254: v1(58.92,36.13) 59.15,36.37 59.15,36.65 58.87,36.93 58.35,36.93 57.63,36.21 57.63,34.56 52.55,29.48 52.55,23.32 52.93,22.94 55.08,22.94 R63.2
  vias: v3(57.41,24.21) v3(57.41,23.45) v3(58.17,24.21) v3(58.17,23.45) v3(58.93,23.45) v3(59.69,24.21) v3(59.69,23.39)
VCC_1.2V_EN: length 3.6
  TOP w0.135: U25.18 53.09,15.01 52.95,14.87 52.95,14.51 52.7,14.27 C101.2 52.7,12.15 R190.1
VCC_1.2V_FB: length 3.4
  TOP w0.305: R191.1 C97.2 R192.2 50.87,17.93 U25.14
VCC_1.2V_PG: length 159.7
  TOP w0.135: v1(51.51,15.27) 51.51,14.35 51.5,14.34 R189.2 52.08,14.34 52.44,14.69 U25.17 ; U3.H10 v2(44.55,66.28)
  ART03 w0.102: v1(45.01,7.59) 43.76,7.59 43.18,7.01 28.4,7.01 23.77,11.63 20.37,11.63 17.5,8.76 8.92,8.76 8.2,8.05 4.39,8.05 2.34,10.11 2.34,59.41 5.07,62.14 11.67,62.14 15.62,66.09 35.66,66.09 v1(37.97,63.78)
  BOTTOM w0.135: v1(51.51,15.27) 51.51,10.03 49.07,7.59 v1(45.01,7.59) ; v1(37.97,63.78) 39.47,65.28 41.96,65.28 42.56,65.87 44.14,65.87 v2(44.55,66.28)
VCC_1.8V: length 9.5
  TOP w0.305: v1(42.06,13.68) 42.06,13.68 U13.B4
  TOP w0.33: v1(47.04,16.23) v1(46.3,16.23) 46.24,16.16 U13.D1 ; U13.E4 v1(42.54,17.78) 42.13,18.19 v1(41.94,18.19)
  BOTTOM w0.254: 41.04,16.19 R245.2 ; 41.04,16.19 40.01,16.19 R262.2 ; 41.04,16.19 42.18,16.19 42.19,16.21 ; R261.2 47.37,15.9 v1(47.04,16.23) 47.04,16.33 46.41,16.97
  vias: v3(30.62,14.62) v3(30.62,13.86) v3(30.62,13.1) v3(31.38,14.62) v3(31.38,13.86) v3(31.38,13.1)
VCC_1.8V_EN: length 2.3
  TOP w0.203: U26.12 34.01,7.77 33.85,7.61 C114.2 R199.1
VCC_2.5V: length 6.9
  TOP w0.254: R68.2 v1(52.41,41.34)
  TOP w0.305: v2(44.54,63.88) 44.54,63.88 U3.F11
  TOP w0.381: U3.G11 v2(43.75,65.48)
  TOP w0.406: TP21.1 39.42,58.14 v1(39.42,57.48)
  BOTTOM w0.305: v2(43.75,65.48) 43.75,64.82 C182.1 43.87,64.58 44.21,64.25 44.21,64.21 v2(44.54,63.88) ; v1(52.41,41.34) 51.41,41.34 R64.2
VCC_2.5V_EN: length 2.7
  BOTTOM w0.203: C113.2 26.8,61.1 R200.1 26.84,62.07 U27.12
VCC_3.3V: length 169.5
  TOP w0.254: U6.43 59.71,65.53 v1(59.31,65.13) ; v1(58.24,71.69) U6.32 ; U6.7 67.61,69.69 67.67,69.64 v1(67.67,69.65) ; U6.55 v1(65.71,65.07) ; U6.17 65.21,74.66 v1(65.23,74.68) ; R79.2 v1(52.49,48.09) ; v1(67.67,71.69) U6.11
  TOP w0.279: v1(67.72,67.51) 67.54,67.69 U6.3
  TOP w0.305: U3.K3 v2(50.95,67.07) ; v1(66.88,31.61) 67.51,31.61 R139.2 ; U3.J11 v2(43.75,67.07) ; U3.J3 v2(50.95,66.27) ; v1(67.67,73.81) 68.33,73.81 68.67,74.16 R29.2 R30.2 ; v1(79.2,33.68) 79.2,33.71 79.12,33.78 R140.1 ; v1(60.22,74.68) 60.22,74.6 60.21,74.59 U6.27 ; R148.2 67.07,56.65 v1(66.9,56.49) ; R143.1 78.99,23.81 78.99,22.71 v1(78.84,22.56) ; v1(78.38,44.78) 78.4,44.77 R135.1 ; R215.1 41.12,72.63 v1(41.12,73.96) ; v1(66.85,35.99) 66.87,36 67.51,36 R137.2 ; U3.L6 v2(48.55,68.67) ; R11.2 31.14,36.7 v1(31.47,36.37) ; R147.2 v1(66.93,54.72) ; U3.G3 v2(50.95,65.48) ; U3.G8 v2(46.15,65.48) ; U3.L7 v2(47.75,68.67) ; R214.1 v1(39.95,74.02) ; U3.C8 v2(46.95,61.47) ; U2.2 v1(20.75,29.16) ; R142.1 78.42,29.15 78.05,28.78 v1(78.05,28.12) ; U3.L8 v2(46.15,68.67) ; R138.1 74.51,39.56 73.23,40.84 v1(72.64,40.84) ; R55.1 39.36,64.05 v1(39.17,63.86) ; U3.C7 v2(47.75,61.47) ; R141.2 v1(66.9,27.01) ; R146.2 v1(66.95,51.78) ; U3.F7 v2(47.75,63.87) ; R144.2 v1(66.9,23) ; U3.C6 v2(48.55,62.28) ; U3.G6 v2(48.55,65.48) ; U3.H11 v2(43.75,66.28) ; U3.H7 v2(47.75,66.28) ; R145.2 v1(66.93,49.57)
  TOP w0.381: R189.1 v1(50.74,13.59) ; R60.1 v1(56.26,79.6)
  TOP w0.508: L12.1 40.54,45.39 v1(39.42,45.39) ; J2.4 47.82,77.55 C18.2 48.36,74.65 v1(48.67,74.96)
  ART03 w0.406: v1(78.05,28.12) 79.2,29.26 v1(79.2,33.68) 79.15,33.73 79.15,36.91 78.38,37.67 v1(78.38,44.78)
  BOTTOM w0.254: v1(67.67,71.69) 67.61,71.69 67.6,71.7 C10.2 ; v1(67.67,69.65) 67.67,69.64 67.61,69.7 C7.2
  BOTTOM w0.305: C151.1 47.64,63.98 v2(47.75,63.87) ; v1(65.23,74.68) 65.2,74.65 C13.2 ; R270.2 R269.2 77.52,11.91 77.5,11.89 v1(77.5,11.63) 78.27,11.63 R265.2 ; R59.2 v1(51.32,75.43) ; v1(50.74,13.59) 50.74,15.38 51.26,15.9 53.31,15.9 55.11,14.11 62.48,14.11 62.5,14.12 v1(63.04,14.12) ; R42.1 49.17,59.65 R43.1 ; R42.1 49.2,58.71 R52.2 49.21,58.25 v2(48.84,57.89) ; R42.1 R33.1 ; 21.34,27.18 21.34,27.81 21.72,28.19 25.7,28.19 26.54,27.36 26.54,24.43 28.57,22.4 R180.2 C84.1 ; C11.2 58.74,64.55 v1(59.31,65.13) ; R56.1 78.65,30.39 78.18,29.92 78.18,28.24 v1(78.05,28.12) ; R77.2 48.43,47.85 52.25,47.85 v1(52.49,48.09) ; C6.2 65.71,65.07 v1(65.71,65.07) ; v1(67.72,67.51) 67.13,68.1 C12.2 ; C157.2 48.55,65.47 v2(48.55,65.48) ; R54.2 44.04,61.91 44.04,61.71 R53.2 42.96,59.72 R51.2 R38.1 42.53,58.32 v1(42.37,58.32) ; R178.1 28.45,16.38 29.87,17.81 29.87,19.25 29.34,19.79 29.34,23.14 28.19,24.28 v1(28.19,25.32) ; v1(44.63,57.94) 45.11,58.42 45.11,59.08 45.61,59.58 R50.2 R39.1 ; v2(43.75,66.28) 43.19,66.83 C146.1 ; v1(60.22,74.68) C9.2 ; v2(43.75,67.07) 43.75,68.12 C155.2 ; R41.1 48.53,62.29 v2(48.55,62.28) ; R61.1 36.23,79.91 36.54,79.6 v1(37.13,79.6) ; C1.1 v1(20.75,29.16) 20.36,29.55 R9.1 ; U4.4 59.44,69.25 59.14,69.55 C2.2 57,70.1 56.77,70.33 v1(55.93,70.33) ; C153.2 47.72,66.25 v2(47.75,66.28) ; R266.2 v1(78.47,7.89)
  BOTTOM w0.381: v1(56.26,79.6) 56.24,79.63 R46.1 ; R47.1 v1(56.31,81.28) ; U16.5 v1(79.48,9.73)
  BOTTOM w0.406: v2(46.15,68.67) 45.95,68.87 C190.1 ; v1(47.8,49.68) R77.2 ; v1(58.24,71.69) 58.66,71.69 58.67,71.68 C8.2 ; L2.1 v1(55.37,68.76)
  BOTTOM w0.508: v1(42.39,74.78) 42.34,74.78 42.32,74.75 C16.2 41.24,75.1 42.82,76.68 J1.4 ; v1(74.07,17.98) U15.5 ; J4.4 62.42,22.31 R280.1
  vias: v1(14.38,48.34) v1(14.38,47.57) v1(14.38,46.79) v1(14.4,45.97) v1(17.96,54.91) v1(17.98,54.08) v1(18.69,54.08) v1(47.8,51.08) v1(47.8,50.37) v1(67.84,61.04) v1(67.82,60.32) v1(68.43,23.6) v1(68.38,22.86) v1(69.11,23.6) v1(69.11,22.89) v1(69.8,23.6) v1(69.82,22.91) v1(70.54,23.6) v1(70.54,22.91) v1(78.11,22.56) v1(78.11,21.84) v1(78.87,21.84) v3(18.77,25.83) v3(18.77,24.94) v3(18.77,24.05) v3(19.66,25.83) v3(19.66,24.94) v3(19.66,24.05) v3(20.42,25.83) v3(20.42,24.94) v3(20.42,24.05) v3(70.69,27.99) v3(70.66,27.2)
VCC_3.3V_EN: length 2.5
  BOTTOM w0.254: R179.1 C88.2 24.83,15.75 U23.18
VCC_3.3V_FB: length 3.7
  BOTTOM w0.305: U23.14 27.59,19.48 R181.2 27.67,20.59 C84.2 R180.1
VCC_3.3V_PG: length 94
  TOP w0.135: U3.H13 42.2,65.53 39.62,65.53 39.32,65.23 39.32,64.8 38.53,64.01 v1(38.53,63.14)
  ART03 w0.102: v1(38.53,63.14) 37.06,63.14 36.65,63.55 29.03,63.55 26.9,65.68 16.28,65.68 13.31,62.71 13.31,56.41 14.88,54.84 14.88,41.58 15.21,41.25 16.74,41.25 18.85,39.14 18.85,38.58 19.25,38.18 21.13,38.18 25.5,33.81 v1(25.5,32.89)
  BOTTOM w0.135: v1(25.5,32.89) 25.5,29.77 29.24,26.03 29.24,24.36 29.9,23.7 29.9,19.91 30.45,19.35 30.45,17.63 28.7,15.88 27.5,15.88 R178.2 26.86,16.51 25.86,16.51 25.48,16.89 U23.17
VCC_5V: length 65.5
  TOP w0.203: 35.2,7.77 35.2,7.77 34.55,7.77 34.41,7.91 U26.13
  TOP w0.305: R235.1 v1(73.84,49.97) ; R190.2 v1(51,12.15)
  TOP w0.356: U25.16 51.71,16.18
  TOP w0.381: v1(29.11,17.91) 26.97,15.77 25.15,15.77 v3(23.93,14.55)
  TOP w0.406: 51.71,16.18 51.43,15.9 51.03,15.9 50.51,15.38 C102.1 49.53,14.99 v1(49.81,14.71) 50.01,14.5 50.01,11.96 50.65,11.33 53.14,11.33 53.85,12.04 v3(53.85,12.32)
  ART03 w0.305: v1(29.11,17.91) 28.42,17.91 26.87,19.46 v1(26.87,20.83) ; v1(73.84,49.97) 71.58,47.71 v1(71.58,35.51)
  BOTTOM w0.203: U27.9 28.27,60.87 28.07,60.67 28.07,60.22 v1(28.24,60.05) ; U27.13 27.8,62.47 27.65,62.62 27.65,62.96 27.66,62.97
  BOTTOM w0.254: U23.16 26.45,18.18 26.97,17.65 C89.1 28.85,17.65 v1(29.11,17.91)
  BOTTOM w0.305: v1(43.92,56.21) 45.44,56.21 L5.1 ; R173.1 72.26,39.31 72.26,40.16 71.08,41.34 C200.2
  BOTTOM w0.508: v1(49.81,14.71) 49.38,15.14 49.38,17.32 v1(51.69,19.64) ; v1(27.43,14.22) 26.48,14.22 R179.2
  vias: v1(25.58,64.57) v1(25.6,63.88) v1(26.29,64.59) v1(26.31,63.88) v1(32.05,7.8) v1(37.44,57.51) v1(38.15,57.51) v1(71.6,34.75) v1(71.6,34.06) v1(71.6,33.27) v1(71.6,32.56) v1(72.31,35.48) v1(72.31,34.75) v1(72.31,34.06) v1(72.31,33.27) v1(72.31,32.56) v1(72.31,31.8) v1(73,35.48) v1(73,34.75) v1(73,34.06) v1(73,33.27) v1(73,32.54) v1(73,31.78) v3(11.99,22.78) v3(11.99,22.05) v3(12.75,22.78) v3(12.78,22.05) v3(21.59,13.77) v3(22.38,13.77) v3(23.14,13.79) v3(23.16,14.55) v3(23.93,13.79) v3(39.96,8.72) v3(39.96,7.96) v3(40.72,8.72) v3(40.72,7.96) v3(41.49,8.72) v3(41.49,7.96) v3(53.85,13.08) v3(54.61,12.32) v3(55.5,12.32)
VCC_5V_IN:
  vias: v1(65.68,79.2) v1(65.68,78.44) v1(66.42,80.64) v1(66.42,79.91) v1(66.37,79.17) v1(66.37,78.44) v1(67.11,80.62) v1(67.11,79.88) v1(67.08,79.2) v1(67.08,78.44) v1(72.64,55.27) v1(72.64,54.58) v1(72.62,53.9) v1(73.33,55.27) v1(73.36,54.58) v1(73.38,53.9) v1(74.02,56.01) v1(74.02,55.27) v1(74.04,54.58) v1(74.07,53.9)
VCCA_ISENSE: length 12.7
  TOP w0.135: U8.5 55.13,44.29 C22.2 51.73,44.3 R72.2 51.71,45.06 51.05,45.72 51.05,49.65 51.8,50.39 52.3,50.39 52.62,50.71 R85.2
VCCINT_ISENSE: length 19.8
  TOP w0.135: R86.2 50.71,50.56 50.44,50.29 50.44,39.75 52.72,37.48 R71.2 C20.2 55.75,38.05 56.5,38.8 U7.5
VCCIO_3.3V_ISENSE: length 5.3
  TOP w0.135: R89.2 53.56,52.78 54.28,52.78 54.62,52.44 R81.2 55.16,51.64 C28.2 55.13,51.08 U11.5
24M_XTALIN: length 2.9
  TOP w0.135: Y1.1 69,68.52 68.95,68.47 C4.1 68.23,68.69 U6.5
24M_XTALOUT: length 5
  TOP w0.135: U6.4 67.82,68.19 68.48,67.54 C5.1 68.95,67.79 70.18,67.79 70.83,67.14 Y1.3
A0+: length 5.6
  TOP w0.135: U32.3 59.02,42.49 59.39,42.85 C169.1 R216.2 R217.2
A1+: length 3.6
  TOP w0.135: R219.2 R218.2 C170.1 60.15,45.92 U32.5
A2+: length 5.5
  TOP w0.135: R221.2 R220.2 C171.1 59.44,49.35 59,48.92 U33.3
A3+: length 4.4
  TOP w0.135: R223.2 R222.2 C172.1 60.57,52.86 59.85,52.86 59.65,52.65 U33.5
A4+: length 5.4
  TOP w0.135: U34.3 58.95,55.24 59.51,55.8 C174.1 R224.2 R225.2
A5+: length 4.4
  TOP w0.135: R227.2 R226.2 C175.1 60.51,59.31 59.81,59.31 59.6,59.1 U34.5
A_GND: length 40.2
  TOP w0.254: C172.2 v1(62.61,52.43) ; C170.2 v1(62.64,45.92) ; R224.1 v1(62.56,54.79) ; C174.2 v1(62.56,55.8) ; R218.1 v1(62.64,44.91) ; R226.1 v1(62.56,57.86) ; C169.2 v1(62.64,42.85) ; R216.1 v1(62.64,41.83) ; C175.2 v1(62.56,58.88) ; R222.1 v1(62.61,51.38) ; R220.1 v1(62.61,48.34) ; C171.2 v1(62.61,49.35)
  TOP w0.305: U8.4 v1(55.13,39.66) ; U32.4 v1(59.67,42) ; U11.4 v1(55.13,46.36) ; R71.1 v1(54.61,35.94) ; C32.2 v1(55.96,57.78) ; U34.4 v1(59.6,55.01) ; U7.4 v1(60.72,38.8) ; C28.1 v1(53.59,51.1) 53.59,52.03 R81.1 ; C39.2 v1(56.69,59.87) ; C35.2 56.26,63.93 v1(56.67,63.53) ; C29.2 v1(55.31,55.88) ; C20.1 v1(55.75,35.94) ; C37.2 52.69,55.31 v1(52.93,55.55) ; v1(52.2,55.63) C36.2 ; U33.4 v1(59.65,48.55) ; C33.2 v1(52.62,52.87) ; C38.2 v1(56.69,61.9) ; R72.1 v1(52.36,43.42) ; C34.2 v1(50.71,51.54) ; U3.E2 v2(51.75,63.07) ; C22.1 v1(56.02,45.12)
  BOTTOM w0.305: C23.1 54.95,39.49 v1(55.13,39.66) ; C19.1 60.55,38.62 v1(60.72,38.8) ; v2(53.67,61.62) 52.96,60.91 C213.1 ; v1(59.03,59.33) 58.56,58.86 C188.2 ; C173.2 58.66,52.59 v1(58.88,52.81) ; C168.2 58.64,46.14 v1(58.85,46.35) ; v1(55.13,46.36) 54.93,46.16 C26.1 ; v1(52.5,49.89) 52.63,50.01 U12.3
  BOTTOM w0.406: C30.2 49.96,52.98 v1(49.94,52.96) ; C212.2 54.17,57.42 C31.2 55.73,56.67 v1(55.98,56.92)
ADC1IN1: length 7.5
  TOP w0.135: U3.D1 53.2,62.67 54.1,61.77 54.1,59.93 54.42,59.61 C32.1 R84.1
ADC1IN2: length 11.3
  TOP w0.135: U3.C2 51.74,61.48 51.74,58.27 51.18,57.71 51.18,53.21 51.73,52.67 C33.1 R85.1
ADC1IN3: length 13.5
  TOP w0.135: R86.1 C34.1 50.72,53.07 50.72,57.91 51.21,58.39 51.21,59.66 50.95,59.93 50.95,63.07 U3.E3
ADC1IN4: length 7.5
  TOP w0.135: U3.E4 50.16,63.89 50.16,64.41 50.39,64.64 53.26,64.64 53.98,63.93 C35.1 R87.1
ADC1IN5: length 6.1
  TOP w0.135: U3.C1 53.21,60.81 53.21,57.29 R88.1 C36.1
ADC1IN6: length 8.2
  TOP w0.135: R89.1 C37.1 51.8,54.9 51.64,55.07 51.64,57.51 52.76,58.62 52.76,60.46 U3.B1
ADC1IN7: length 5.1
  TOP w0.135: R90.1 C38.1 54.99,62.06 54.99,62.26 52.97,64.27 U3.F1
ADC1IN8: length 6.4
  TOP w0.135: R91.1 C39.1 54.56,60.46 54.56,61.98 53.06,63.47 U3.E1
ANA_VREF: length 10.1
  TOP w0.381: R308.1 26.07,13.13 19.58,13.13 19.15,12.7 J5.8
ANAIN1: length 10.2
  TOP w0.135: U3.D2 51.75,62.27 52.43,62.27 53.64,61.06 53.64,59.58 53.78,59.44 53.78,56.55 54.42,55.92 C29.1 R83.1
ARDUINO_ADC_SCL: length 49.3
  TOP w0.135: v2(39.84,34.48) U1.D8 ; R215.2 41.43,71.18 41.43,69.16 v1(41.83,68.76) 42.09,68.76 42.17,68.67 42.95,68.67 U3.L12
  ART03 w0.102: v2(39.84,34.48) 39.45,34.87 39.45,35.92 38.56,36.81 38.56,45.36 39.19,46 40.06,46 44.98,50.93 44.98,56.59 44.07,57.51 44.07,58.72 42.55,60.25 42.55,61.21 42.09,61.67 42.09,64.19 41.25,65.02 41.25,68.17 v1(41.83,68.76)
  BOTTOM w0.135: R279.2 38.99,37.52 39.44,37.07 39.44,34.98 39.84,34.58 v2(39.84,34.48)
ARDUINO_ADC_SDA: length 47.7
  TOP w0.135: U3.K11 43.75,67.88 41.94,67.88 v1(41.86,67.79) 41.61,67.79 40.59,68.81 40.59,70.61 39.95,71.25 R214.2 ; U1.C8 v2(39.84,35.28)
  ART03 w0.102: v2(39.84,35.28) 39.75,35.37 39.75,36.04 39.14,36.65 39.14,44.3 45.39,50.55 45.39,58.24 43.03,60.6 43.03,61.44 42.47,62 42.47,64.57 42.19,64.85 42.19,67.46 v1(41.86,67.79)
  BOTTOM w0.135: v2(39.84,35.28) 39.84,37.87 R278.2
ARDUINO_AMP0: length 19.6
  TOP w0.135: U32.2 58.37,40.37 58.27,40.26 57.81,40.26 57.72,40.35 U32.1 57.72,43.16 56.96,43.93 56.96,46.11 55.98,47.09 55.98,51.99 54.64,53.34 54.2,53.34 53.75,53.8 53.75,55.87 R88.2
ARDUINO_AMP1: length 12.4
  TOP w0.135: R83.2 55.31,53.51 56.54,52.27 56.54,47.35 57.58,46.3 58.09,46.3 58.37,46.02 U32.7 58.37,44.8 58.55,44.63 58.87,44.63 59.02,44.78 U32.6
ARDUINO_AMP2: length 11.7
  TOP w0.135: U33.2 58.35,47.19 58.25,47.09 57.89,47.09 57.7,47.28 U33.1 57.7,50.1 57.1,50.7 57.1,52.59 56.16,53.53 56.16,55.92 R84.2
ARDUINO_AMP3: length 10.4
  TOP w0.135: U33.6 59,51.18 58.82,51 58.61,51 58.35,51.26 U33.7 58.35,52.5 58.09,52.76 57.73,52.76 56.79,53.7 56.79,56.46 56.49,56.77 56.49,58.41 R91.2
ARDUINO_AMP4: length 9.8
  TOP w0.135: U34.2 58.3,53.64 58.19,53.53 57.83,53.53 57.65,53.71 U34.1 57.65,56.45 57.05,57.05 57.05,59.05 57.38,59.39 57.38,60.3 56.79,60.88 R90.2
ARDUINO_AMP5: length 7.8
  TOP w0.135: R87.2 56.55,62.92 58.3,61.17 U34.7 58.3,57.78 58.48,57.61 58.78,57.61 58.95,57.78 U34.6
ARDUINO_ANA0: length 3.1
  TOP w0.135: J6.1 63.3,40.82 R217.1
ARDUINO_ANA1: length 3.3
  TOP w0.135: J6.2 62.79,43.87 R219.1
ARDUINO_ANA2: length 4
  TOP w0.135: R221.1 62.33,47.32 63.58,46.08 63.58,45.62 J6.3
ARDUINO_ANA3: length 4.8
  TOP w0.135: J6.4 63.25,48.49 63.25,49.99 62.87,50.37 R223.1
ARDUINO_ANA4: length 5.6
  TOP w0.135: J6.5 63.27,51 63.27,53.24 62.74,53.77 R225.1
ARDUINO_ANA5: length 6.3
  TOP w0.135: R227.1 63.09,56.82 63.72,56.2 63.72,54.37 64.49,53.59 J6.6
ARDUINO_IO0: length 28.9
  TOP w0.137: U1.B1 30.85,39.47 25.44,39.47 22.9,42.01 20.35,42.01 18.24,44.12 18.24,50.32 J7.1
ARDUINO_IO1: length 27.9
  TOP w0.137: U1.C2 35.04,35.28 34.19,35.28 30.45,39.01 25.22,39.01 22.71,41.53 20.19,41.53 17.75,43.97 17.75,48.26 J7.2
ARDUINO_IO2: length 28
  TOP w0.135: J7.3 17.29,46.19 17.29,43.8 20.22,40.87 v1(22.56,40.87) ; U1.F3 v2(35.84,32.88)
  ART03 w0.102: v1(22.56,40.87) 24.89,40.87 33.41,32.35 35.31,32.35 v2(35.84,32.88)
ARDUINO_IO3: length 26
  TOP w0.135: U1.D1 33.2,34.08 31.88,35.41 26.8,35.41 25.76,36.45 19.1,36.45 18.75,36.8 18.75,41.53 16.23,44.04 J7.4
ARDUINO_IO4: length 25.9
  TOP w0.135: J7.5 18.26,40.13 18.26,36.37 18.67,35.97 25.5,35.97 26.52,34.95 31.67,34.95 33.66,32.97 33.66,32.77 34.29,32.14 34.98,32.14 U1.G2
ARDUINO_IO5: length 22.9
  TOP w0.135: J7.6 17.73,38.13 17.73,36.04 18.29,35.48 25.3,35.48 26.29,34.49 31.46,34.49 34.28,31.68 U1.G1
ARDUINO_IO6: length 26
  TOP w0.137: U1.J2 35.04,29.68 33.09,29.68 31.6,31.17 29.46,31.17 28.3,32.33 19.74,32.33 18.64,33.43 15.64,33.43 14.88,34.19 14.88,35.74 J7.7
ARDUINO_IO7: length 20.3
  TOP w0.137: J7.8 18.64,34.54 19.68,33.5 27.03,33.5 27.74,32.79 28.47,32.79 29.64,31.62 31.8,31.62 33.34,30.08 U1.J1
ARDUINO_IO8: length 21.2
  TOP w0.137: U1.K2 35.04,28.88 32.54,28.88 31.19,30.23 29.08,30.23 28.42,30.89 19.76,30.89 18.8,31.85 v1(18.24,31.85)
  BOTTOM w0.135: J5.1 17.6,31.85 v1(18.24,31.85)
ARDUINO_IO9: length 32.2
  TOP w0.135: U1.K5 v2(37.44,28.88)
  ART03 w0.102: v2(37.44,28.88) 37.03,29.29 35.38,29.29 34.95,28.85 29.87,28.85 29.36,29.36 29.36,30.23 27.57,32.02 25.71,32.02 23.88,33.86 v1(23.88,34.54)
  BOTTOM w0.135: J5.2 14.86,29.31 14.86,31.6 15.8,32.54 21.87,32.54 v1(23.88,34.54)
ARDUINO_IO10: length 35.6
  TOP w0.135: U1.L4 v2(36.64,28.08)
  ART03 w0.102: v2(36.64,28.08) 36.25,27.69 33.96,27.69 33.58,27.3 33.12,27.3 32.38,28.04 29.53,28.04 29.51,28.07 29.5,28.07 28.55,29.02 28.55,29.11 28.55,29.62 27.74,30.43 25.7,30.43 22.23,33.91 v1(22.23,34.8)
  BOTTOM w0.135: v1(22.23,34.8) 20.6,33.17 15.67,33.17 14.35,31.85 14.35,27.28 J5.3
ARDUINO_IO11: length 90.3
  TOP w0.137: v1(13.59,33.93) 14.61,32.92 18.42,32.92 19.46,31.88 28.12,31.88 29.29,30.71 31.34,30.71 32.77,29.28 U1.K1
  BOTTOM w0.135: J18.4 40.41,53.67 40.41,52.04 39.62,51.26 34.72,51.26 32.94,53.04 32.94,55.35 31.37,56.92 26.19,56.92 25.7,57.4 20.98,57.4 20.52,56.95 17.93,56.95 13.59,52.6 v1(13.59,33.93) 13.84,33.68 13.84,26.29 16.23,23.9 J5.4
ARDUINO_IO12: length 88.4
  TOP w0.137: v1(13.23,32.61) 14.22,31.62 17.14,31.62 18.87,29.9 28.09,29.9 30.61,27.38 33.63,27.38 34.32,28.07 35.03,28.07 U1.L2
  BOTTOM w0.135: J5.5 16.18,20.32 14.99,21.51 14.99,24.38 13.23,26.14 v1(13.23,32.61) 13.08,32.77 13.08,52.76 17.75,57.43 20.32,57.43 20.88,57.99 24.21,57.99 24.31,58.09 28.3,58.09 28.8,57.58 31.39,57.58 32.13,56.85 33.12,56.85 33.43,56.54 33.43,53.55 34.53,52.45 J18.1
ARDUINO_IO13: length 94.4
  TOP w0.137: v1(12.6,33.93) 14.4,32.13 17.27,32.13 18.97,30.43 28.24,30.43 30.19,28.48 U1.L1
  BOTTOM w0.135: J18.3 37.82,53.72 34.34,53.72 33.96,54.1 33.96,57.63 33.43,58.17 29.13,58.17 28.71,58.59 23.99,58.59 23.88,58.47 19.68,58.47 19.15,57.94 17.55,57.94 14.91,55.3 12.6,52.98 v1(12.6,33.93) 12.6,25.93 14.53,24 14.53,19.46 16.21,17.78 J5.6
ARDUINO_RSTN: length 141.1
  TOP w0.135: v2(35.84,28.08) U1.L3
  ART03 w0.102: v2(35.84,28.08) 33.64,28.08 v1(33.48,27.91) 32.94,28.45 29.69,28.45 28.96,29.18 28.96,29.95 27.53,31.37 25.68,31.37 23.39,33.66 23.39,34.67 20.35,37.72 19.13,37.72 18.29,38.56 18.29,38.91 16.41,40.79 14.83,40.79 13.89,41.73 13.89,52.22 v1(14.4,52.73)
  BOTTOM w0.135: v1(33.48,27.91) 33.48,27.1 31.6,25.22 31.6,21.06 32.08,20.57 32.08,17.25 29.74,14.91 29.74,12.17 30.76,11.15 34.57,11.15 38.63,7.09 49.35,7.09 52.85,10.58 56.81,10.58 59.79,13.56 63.96,13.56 65.56,15.16 65.56,20.78 J4.3 ; J18.5 39.95,50.77 34.54,50.77 32.44,52.88 32.44,55.22 31.27,56.39 24.33,56.39 23.8,56.92 21.31,56.92 20.78,56.39 18.06,56.39 v1(14.4,52.73) ; R288.2 35.76,28 v2(35.84,28.08)
ARDUINO_SCL: length 42.6
  TOP w0.135: R277.2 30.84,26.24 30.35,26.72 28.65,26.72 27.41,25.48 22.66,25.48 21.26,26.87 18.8,26.87 18.14,27.53 v1(18.14,29.31)
  TOP w0.137: U1.N1 34.58,26.82 32.69,26.82 32.11,26.24 R277.2
  BOTTOM w0.135: v1(18.14,29.31) 17.81,28.98 17.81,12.09 17.32,11.61 17.32,8.71 J5.10
ARDUINO_SDA: length 42.2
  TOP w0.135: R276.2 30.87,24.52 30.74,24.38 28.02,24.38 27.38,25.02 22.45,25.02 21.06,26.42 18.31,26.42 17.4,27.33 v1(17.4,29.34)
  TOP w0.137: U1.N2 35.04,26.48 33.03,26.48 31.98,25.43 31.45,25.43 30.87,24.85 R276.2
  BOTTOM w0.135: J5.9 16.23,11.15 17.32,12.25 17.32,29.26 v1(17.4,29.34)
C10_AS_ASDO: length 16.1
  TOP w0.137: U2.15 20.75,38 21.29,38.53 30.23,38.53 33.88,34.88 U1.C1
C10_AS_CSN: length 16.9
  TOP w0.135: v1(28.5,36.2) 28.83,35.86 32.14,35.86 33.51,34.48 35.04,34.48 U1.D2 ; U2.7 27.1,28.88 v1(26.75,29.24)
  BOTTOM w0.135: v1(26.75,29.24) 26.75,34.44 v1(28.5,36.2)
C10_AS_DATA0: length 11.1
  TOP w0.135: U1.H2 35.07,31.25 34.08,31.25 31.32,34.01 v1(28.37,34.01)
  BOTTOM w0.135: R10.1 v1(28.37,34.01)
C10_AS_DCLK: length 22.2
  TOP w0.135: U1.H1 33.81,30.88 31.17,33.53 27.79,33.53 27.3,34.01 20.37,34.01 v1(19.48,34.9) ; U2.16 v1(19.48,38.89)
  BOTTOM w0.135: v1(19.48,34.9) v1(19.48,38.89)
C10_CLK50M: length 22.1
  TOP w0.135: R162.2 v1(38.18,49.68) ; v2(34.24,33.68) U1.E1
  ART03 w0.102: v2(34.24,33.68) 32.59,35.33 32.59,46.66 35.61,49.68 v1(38.18,49.68)
C10_CLK50M_R: length 2.6
  TOP w0.135: R162.1 38.18,46.69 v1(38.2,46.66)
  BOTTOM w0.135: U20.5 v1(38.2,46.66)
C10_CLK_ADJ: length 38
  TOP w0.137: U1.E16 47.62,33.28 49.4,31.5 51.21,31.5 52.4,30.3 57.81,30.3 61.77,26.34 61.77,24.89 62.33,24.33 62.33,23.19 62.69,22.83 62.69,21.41 63.63,20.47 66.32,20.47 v1(66.55,20.24)
  BOTTOM w0.135: v1(66.55,20.24) 66.55,21.44 66.29,21.69 66.29,23.22 67.61,24.54 R155.2
C10_CONF_DONE: length 83.6
  TOP w0.135: v2(45.44,31.28) U1.H14 ; U3.L2 51.73,68.66 52.6,68.66 54.53,66.73 56.49,66.73 58.27,64.95 58.27,64.39 59.36,63.3 65.63,63.3 67.39,61.54 68.38,61.54 v1(68.81,61.11)
  ART03 w0.102: v2(45.44,31.28) 46.01,30.71 60.58,30.71 63.2,28.09 67.59,28.09 71.12,31.62 71.12,49.07 69.77,50.42 69.77,53.92 68.22,55.47 68.22,59.21 68.81,59.79 v1(68.81,61.11)
  BOTTOM w0.135: R16.2 46.64,30.45 46.64,31.44 46.41,31.68 46.05,31.68 45.66,31.28 v2(45.44,31.28)
C10_CRC_ERROR: length 83.6
  TOP w0.135: U3.M1 52.82,69.07 54.71,67.18 56.67,67.18 58.78,65.07 58.78,64.54 59.56,63.75 65.89,63.75 67.64,62 v1(68.83,62) ; v2(46.24,32.08) U1.G15
  ART03 w0.102: v2(46.24,32.08) 46.65,31.67 47.73,31.67 48.29,31.12 60.86,31.12 63.42,28.55 67.46,28.55 70.71,31.8 70.71,48.54 69.37,49.89 69.37,53.62 67.82,55.17 67.82,59.41 68.33,59.92 68.33,61.49 v1(68.83,62)
  BOTTOM w0.135: R246.2 48.3,30.81 48.3,31.58 47.4,32.49 46.65,32.49 v2(46.24,32.08)
C10_DEV_OE: length 3.7
  TOP w0.135: U1.J16 47.08,29.64 49.75,29.64 R207.2
C10_INIT_DONE: length 78
  TOP w0.135: U3.K2 51.76,67.89 52.73,67.89 54.36,66.27 56.29,66.27 57.73,64.82 57.73,64.24 59.13,62.84 62.81,62.84 63.7,61.95 66.17,61.95 v1(67.08,61.04) ; v2(47.04,32.08) U1.G16
  ART03 w0.102: v1(67.08,61.04) 67.36,60.76 67.36,54.97 68.96,53.37 68.96,49.38 70.31,48.03 70.31,32.03 67.56,29.29 66.14,29.29 64.92,30.51 63.78,30.51 63.23,29.96 62.6,29.96 61.04,31.52 48.54,31.52 48.01,32.05 48.01,32.08 v2(47.04,32.08)
  BOTTOM w0.135: v2(47.04,32.08) 47.62,31.5 R21.2
C10_JTAG_TCK: length 72.8
  TOP w0.135: U3.E10 44.59,63.12 42.49,63.12 41.68,62.31 v1(37.52,62.31) ; U1.H3 35.79,30.43 33.63,30.43 31.8,32.26 R6.1 30.7,32.6 v1(30.28,33.02)
  ART03 w0.102: v1(30.28,33.02) 29.69,32.44 29.06,32.44 22,39.5 21.44,39.5 17.53,43.41 17.53,52.58 15.88,54.23 15.88,59.39 17.09,60.6 28.75,60.6 29.24,60.12 35.33,60.12 v1(37.52,62.31)
C10_JTAG_TDI: length 69.4
  TOP w0.135: v2(36.64,31.28) U1.H4 ; U3.A12 42.91,60.71 37.92,60.71 35.56,58.34 35.56,55.35 v1(34.54,54.33)
  ART03 w0.102: v2(36.64,31.28) 36.25,31.67 33.51,31.67 29.67,35.5 28.05,35.5 27.56,35.99 27.56,37.4 24.63,40.34 22.02,40.34 19.76,42.6 19.76,44.55 18.41,45.9 18.41,50.04 19.89,51.51 19.89,55.65 21.16,56.92 22.2,56.92 22.78,56.34 31.95,56.34 32.69,55.6 33.27,55.6 v1(34.54,54.33)
  BOTTOM w0.135: v2(36.64,31.28) 36.35,30.99 34.72,30.99 34.58,30.85 R4.2
C10_JTAG_TDO: length 77.2
  TOP w0.135: v1(36.75,62.31) 37.26,61.8 41.94,61.8 42.41,62.27 42.94,62.27 U3.D12 ; v2(36.64,29.68) U1.J4
  ART03 w0.102: v2(36.64,29.68) 35.99,30.33 32.66,30.33 31.39,31.6 29.31,31.6 21.82,39.09 21.21,39.09 17.17,43.13 16.36,43.13 15.29,44.2 15.29,55.47 14.43,56.34 14.43,60.38 19.33,65.28 26.59,65.28 28.73,63.14 35.92,63.14 v1(36.75,62.31)
C10_JTAG_TMS: length 81.4
  TOP w0.135: U1.J5 v2(37.44,29.68) ; U3.D9 45.3,62.23 43.94,62.23 43.69,61.98 43.69,61.59 43.56,61.47 42.14,61.47 41.94,61.26 37.72,61.26 35.1,58.65 35.1,55.63 v1(34.59,55.12)
  ART03 w0.102: v1(34.59,55.12) 33.78,55.93 33.78,59.13 33.35,59.56 27.46,59.56 27.15,59.87 17.17,59.87 16.36,59.06 16.36,54.97 17.98,53.34 17.98,43.66 21.72,39.93 22.15,39.93 27.51,34.57 29.44,34.57 33.07,30.94 36.18,30.94 v2(37.44,29.68)
  BOTTOM w0.135: R7.2 37.43,29.69 v2(37.44,29.68)
